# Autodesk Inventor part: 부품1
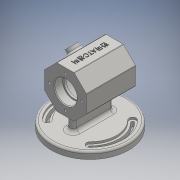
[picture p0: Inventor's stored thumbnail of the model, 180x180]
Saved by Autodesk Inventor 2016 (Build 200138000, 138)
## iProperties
Created: 2017-06
Part Number: 부품1
Material: 일반
Document SubType Name: Modeling
Designer: USER
Density: 1 g/cm^3
Appearance: 기본값
Author: USER
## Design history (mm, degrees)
sketch "스케치1"
  geometry: C1 r 55 at (0, 0); 1 further point
  constraints: 1 centre point, 1 coincident
  dimensions: "d0" = 110 diameter of C1
extrude "돌출1" new body sketch "스케치1" distance "d1" = 10; taper "d2" = 0 deg
sketch "스케치2"
  geometry: L1 (-55, 0)-(55, 0) reference; L2 (0, 62)-(0, 94.472); L3 (0, 62)-(-12.426, 92); L4 (0, 62)-(12.426, 92); L5 (12.426, 92)-(-12.426, 92); L6 (0, 62)-(-30, 74.426); L7 (0, 62)-(-30, 49.574); L8 (0, 62)-(-12.426, 32); L9 (0, 62)-(12.426, 32); L10 (0, 62)-(30, 49.574); L11 (0, 62)-(30, 74.426); L12 (-12.426, 92)-(-30, 74.426); L13 (-30, 49.574)-(-30, 74.426); L14 (-30, 49.574)-(-12.426, 32); L15 (-12.426, 32)-(12.426, 32); L16 (12.426, 32)-(30, 49.574); L17 (30, 49.574)-(30, 74.426); L18 (30, 74.426)-(12.426, 92); 3 further points
  constraints: 34 end point, 2 perpendicular, 2 vertical alignment, 1 coincident, 1 midpoint, 1 point on line, 1 vertical, 12 other
  dimensions: "d4" = 62 distance from line of point (0, 62) L1; "d10" = 22.5 deg angle of L2 L3; "d11" = 22.5 deg angle of L2 L4; "d12" = 92 distance from line of L4.end L1; "d13" = 45 deg angle of L3 L6; "d14" = 45 deg angle of L7 L6; "d15" = 45 deg angle of L7 L8; "d16" = 45 deg angle of L8 L9; "d17" = 45 deg angle of L10 L9; "d18" = 45 deg angle of L11 L10
extrude "돌출2" join sketch "스케치2" stored distance "d19" = 70; taper "d20" = 0 deg
sketch "스케치3"
  geometry: L1 (0, -24)-(0, 24); L2 (-5, -24)-(-5, 24); L3 (5, 24)-(5, -24); A1 r 5 centre (0, -24) between (-5, -24) and (5, -24); A2 r 5 centre (0, 24) between (5, 24) and (-5, 24); 3 further points
  constraints: 8 end point, 4 point on circle, 4 tangent, 2 centre point, 2 midpoint, 1 coincident, 1 horizontal alignment, 1 parallel, 1 vertical
  dimensions: "d21" = 48 distance of L1.end L1.start; "d22" = 5 radius of A1
extrude "돌출3" join sketch "스케치3" stored distance "d23" = 70; taper "d24" = 0 deg
sketch "스케치4"
  geometry: L1 (12.426, 92)-(-12.426, 92) reference; L2 (-12.426, 92)-(-30, 74.426) reference; L3 (-30, 74.426)-(-30, 49.574) reference; L4 (-30, 49.574)-(-12.426, 32) reference; L5 (-12.426, 32)-(12.426, 32) reference; L6 (12.426, 32)-(30, 49.574) reference; L7 (30, 49.574)-(30, 74.426) reference; L8 (30, 74.426)-(12.426, 92) reference; L9 (-55, 0)-(55, 0) reference; C1 r 16 at (0, 62); 2 further points
  constraints: 1 centre point, 1 midpoint, 1 vertical alignment
  dimensions: "d25" = 32 diameter of C1; "d26" = 62 distance from line of C1.centre L9
extrude "돌출4" cut sketch "스케치4" distance "d27" = 12; taper "d28" = 0 deg
sketch "스케치5"
  geometry: C1 r 16 at (0, 0) reference; C2 r 14 at (0, 0); 1 further point
  constraints: 1 centre point, 1 coincident
  dimensions: "d29" = 28 diameter of C2
extrude "돌출5" cut sketch "스케치5" distance "d30" = 3; taper "d31" = 0 deg
node "작업 평면1"
sketch "스케치6"
  geometry: L1 (12.426, 92)-(-12.426, 92) reference; L2 (-12.426, 92)-(-30, 74.426) reference; L3 (-30, 74.426)-(-30, 49.574) reference; L4 (-30, 49.574)-(-12.426, 32) reference; L5 (-12.426, 32)-(12.426, 32) reference; L6 (12.426, 32)-(30, 49.574) reference; L7 (30, 49.574)-(30, 74.426) reference; L8 (30, 74.426)-(12.426, 92) reference; C1 r 16 at (0, 62) reference; C2 r 25 at (0, 62); 1 further point
  constraints: 1 centre point, 1 coincident
  dimensions: "d32" = 50 diameter of C2
extrude "돌출6" cut sketch "스케치6" stored distance "d33" = 40; taper "d34" = 0 deg
sketch "스케치8"
  geometry: L1 (0, 0)-(-30.406, -30.406); L2 (0, 0)-(-30.406, 30.406); L3 (0, 0)-(-63.999, 0); A1 r 43 centre (0, 0) between (-30.406, 30.406) and (-30.406, -30.406); A2 r 48 centre (0, 0) between (-33.941, 33.941) and (-33.941, -33.941); A3 r 38 centre (0, 0) between (-26.87, 26.87) and (-26.87, -26.87); A4 r 5 centre (-30.406, 30.406) between (-26.87, 26.87) and (-33.941, 33.941); A5 r 5 centre (-30.406, -30.406) between (-33.941, -33.941) and (-26.87, -26.87); 2 further points
  constraints: 11 point on circle, 6 end point, 5 centre point, 4 tangent, 1 coincident, 1 horizontal, 1 horizontal alignment
  dimensions: "d35" = 38 radius of A3; "d36" = 48 radius of A2; "d37" = 90 deg angle of L2 L1
extrude "돌출7" cut sketch "스케치8" distance "d38" = 3; taper "d39" = 0 deg
sketch "스케치9"
  geometry: A1 r 48 centre (0, 0) between (-33.941, 33.941) and (-33.941, -33.941) reference; A2 r 5 centre (-30.406, -30.406) between (-33.941, -33.941) and (-26.87, -26.87) reference; A3 r 38 centre (0, 0) between (-26.87, 26.87) and (-26.87, -26.87) reference; A4 r 5 centre (-30.406, 30.406) between (-26.87, 26.87) and (-33.941, 33.941) reference; A5 r 45 centre (0, 0) between (-31.82, 31.82) and (-31.82, -31.82); A6 r 2 centre (-30.406, 30.406) between (-28.991, 28.991) and (-31.82, 31.82); A7 r 41 centre (0, 0) between (-28.991, 28.991) and (-28.991, -28.991); A8 r 2 centre (-30.406, -30.406) between (-31.82, -31.82) and (-28.991, -28.991); 1 further point
  constraints: 8 point on circle, 4 centre point, 3 other
  dimensions: "d40" = 3 radial gap between concentric circles of A1 A5
extrude "돌출8" cut sketch "스케치9" stored distance "d41" = 3; taper "d42" = 0 deg
node "작업 평면2"
chamfer "모따기1" distance "d43" = 1; stored, may be unused: second distance "d44" = 2, angle "d45" = 45 deg
fillet "모깎기1" dims "d46" = 3
fillet "모깎기2" dims "d47" = 0.3
sketch "스케치10" dims "d48" = 46
  geometry: C1 r 17 at (0, 62) reference; 3 further points
  constraints: 2 vertical alignment, 1 coincident, 2 other
hole "구멍1" sketch "스케치10" at (0, 85) diameter "d49" = 3.242; stored, may be unused: countersink angle "d53" = 90 deg, drill point angle "d55" = 118 deg; dims "d50" = 8, "d51" = 4, "d52" = 2, "d54" = 10
sketch "스케치11"
  geometry: L1 (0, 62)-(0, 102.776); L2 (0, 62)-(-29.041, 91.041); C1 r 25 at (0, 62) reference; 1 further point
  constraints: 4 end point, 1 vertical
  dimensions: "d59" = 45 deg angle of L1 L2
node "작업 평면4"
sketch "스케치16"
  geometry: L1 (-24.853, 70)-(0, 70) reference; C1 r 8 at (-12.426, 35); 2 further points
  constraints: 1 centre point, 1 horizontal alignment, 1 midpoint, 1 vertical alignment
  dimensions: "d67" = 16 diameter of C1
extrude "돌출11" join sketch "스케치16" distance "d68" = 7; taper "d69" = 0 deg
sketch "스케치17"
  geometry: C1 r 8 at (0, 0) reference; C2 r 4 at (0, 0); 1 further point
  constraints: 1 centre point, 1 coincident
  dimensions: "d70" = 8 diameter of C2
extrude "돌출12" cut sketch "스케치17" stored distance "d71" = 7; taper "d72" = 0 deg
fillet "모깎기3" dims "d73" = 3
fillet "모깎기4" dims "d74" = 1
fillet "모깎기5" dims "d75" = 3
fillet "모깎기6" dims "d76" = 5
sketch "스케치20"
  geometry: L1 (0, 0)-(24.024, 0) reference; 2 further points
  constraints: 1 coincident, 1 other
feature "엠보싱1" sketch "스케치20" dims "d0" = 110, "d78" = 0.5, "d79" = 0
node "작업 평면5"
chamfer "모따기2" distance "d80" = 1; stored, may be unused: second distance "d81" = 2, angle "d82" = 45 deg
node "솔리드1"
mirror "대칭1"
mirror "대칭2"
pattern_circular "원형 패턴1" dims angle "d57" = 360 deg
mirror "대칭3"
node "투영된 루프1"
node "투영된 루프2"
node "투영된 루프3"
node "투영된 루프4"
node "투영된 루프6"
other parameters: "d66" = 7
